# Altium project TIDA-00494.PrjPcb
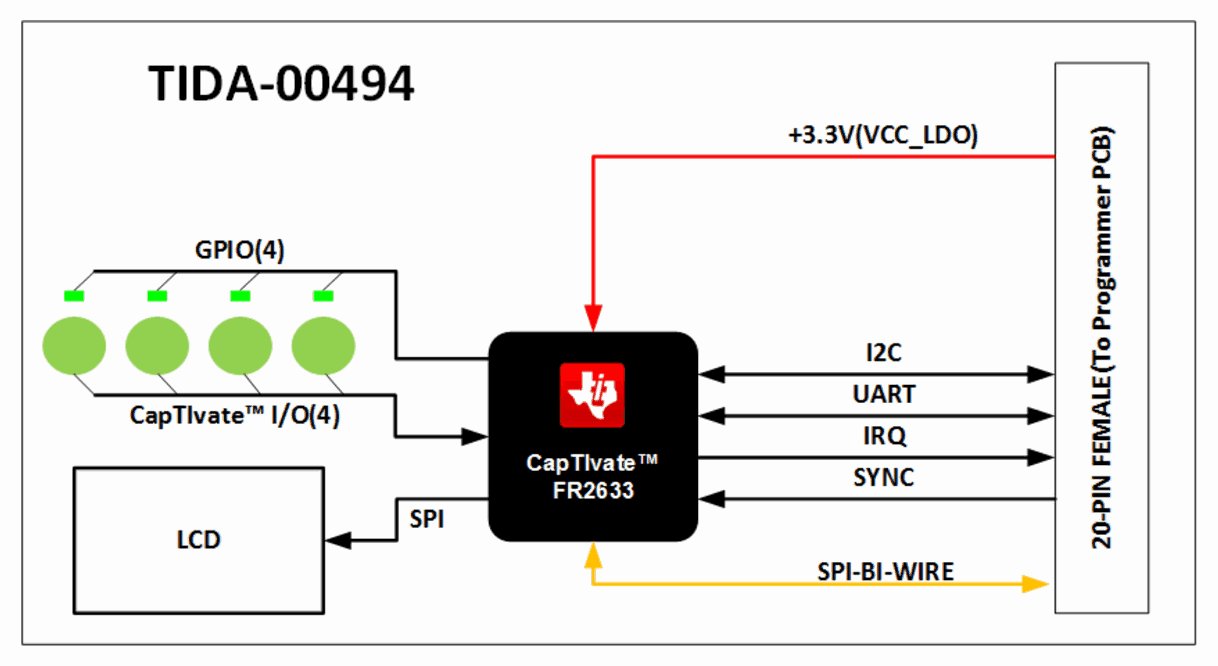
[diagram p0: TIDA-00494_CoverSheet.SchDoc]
CopyrightYear: 2016; PCB_Layout: Giovanni Campanella; PCB_Rev: E1; PRJ_Customer: Public Release; PRJ_Engineer: Giovanni Campanella; PRJ_Number: TIDA-00494; PRJ_Title: Touch through Glass with Display; SCH_Rev: E1; TechSupport: http://www.ti.com/support; TID: TIDA-00494
3 sheets, 49 parts. Net scope: global (net labels, ports and power ports of the same name join across sheets).
Board file: TIDA-00494.PcbDoc
Sheets:
  TIDA-00494_CoverSheet.SchDoc
  TIDA-00494_Schematic.SchDoc
  TIDA-00494_Hardware.SchDoc

## Sheet TIDA-00494_CoverSheet.SchDoc: Block Diagram TIDA-00494
size 431 x 279 mm; Date: Not shown in title block; ApprovedBy: Not shown in title block; CheckedBy: Not shown in title block; Author: Not shown in title block; CompanyName: Not shown in title block; DrawnBy: Giovanni Campanella; Engineer: Not shown in title block; Organization: Not shown in title block; Address1: Not shown in title block; Address2: Not shown in title block; Address3: Not shown in title block; Address4: Not shown in title block; DocumentNumber: 1; Revision: Use project parameter SCH_Rev; SheetNumber: 1; SheetTotal: 3; PageSetup: Record=PageOptions¦CenterHorizontal=True¦CenterVertical=True¦PrintScale=1.00¦XCorrection=1.00¦YCorrection=1.00¦PrintKind=0¦BorderSize=5000000¦LeftOffset=0¦BottomOffset=0¦Orientation=2¦PaperLength=1000¦PaperWidth=1000¦Scale=100¦PaperSource=15¦PrintQuality=600¦MediaType=1¦DitherType=10¦PaperKind=Letter¦PrintScaleMode=1

## Sheet TIDA-00494_Schematic.SchDoc: Schematic TIDA-00494
size 431 x 279 mm; Date: Not shown in title block; ApprovedBy: Not shown in title block; CheckedBy: Not shown in title block; Author: Not shown in title block; CompanyName: Not shown in title block; DrawnBy: Giovanni Campanella; Engineer: Not shown in title block; Organization: Not shown in title block; Address1: Not shown in title block; Address2: Not shown in title block; Address3: Not shown in title block; Address4: Not shown in title block; DocumentNumber: 2; Revision: Use project parameter SCH_Rev; SheetNumber: 2; SheetTotal: 3; PageSetup: Record=PageOptions¦CenterHorizontal=True¦CenterVertical=True¦PrintScale=1.00¦XCorrection=1.00¦YCorrection=1.00¦PrintKind=0¦BorderSize=5000000¦LeftOffset=0¦BottomOffset=0¦Orientation=2¦PaperLength=1000¦PaperWidth=1000¦Scale=100¦PaperSource=15¦PrintQuality=600¦MediaType=1¦DitherType=10¦PaperKind=Letter¦PrintScaleMode=1
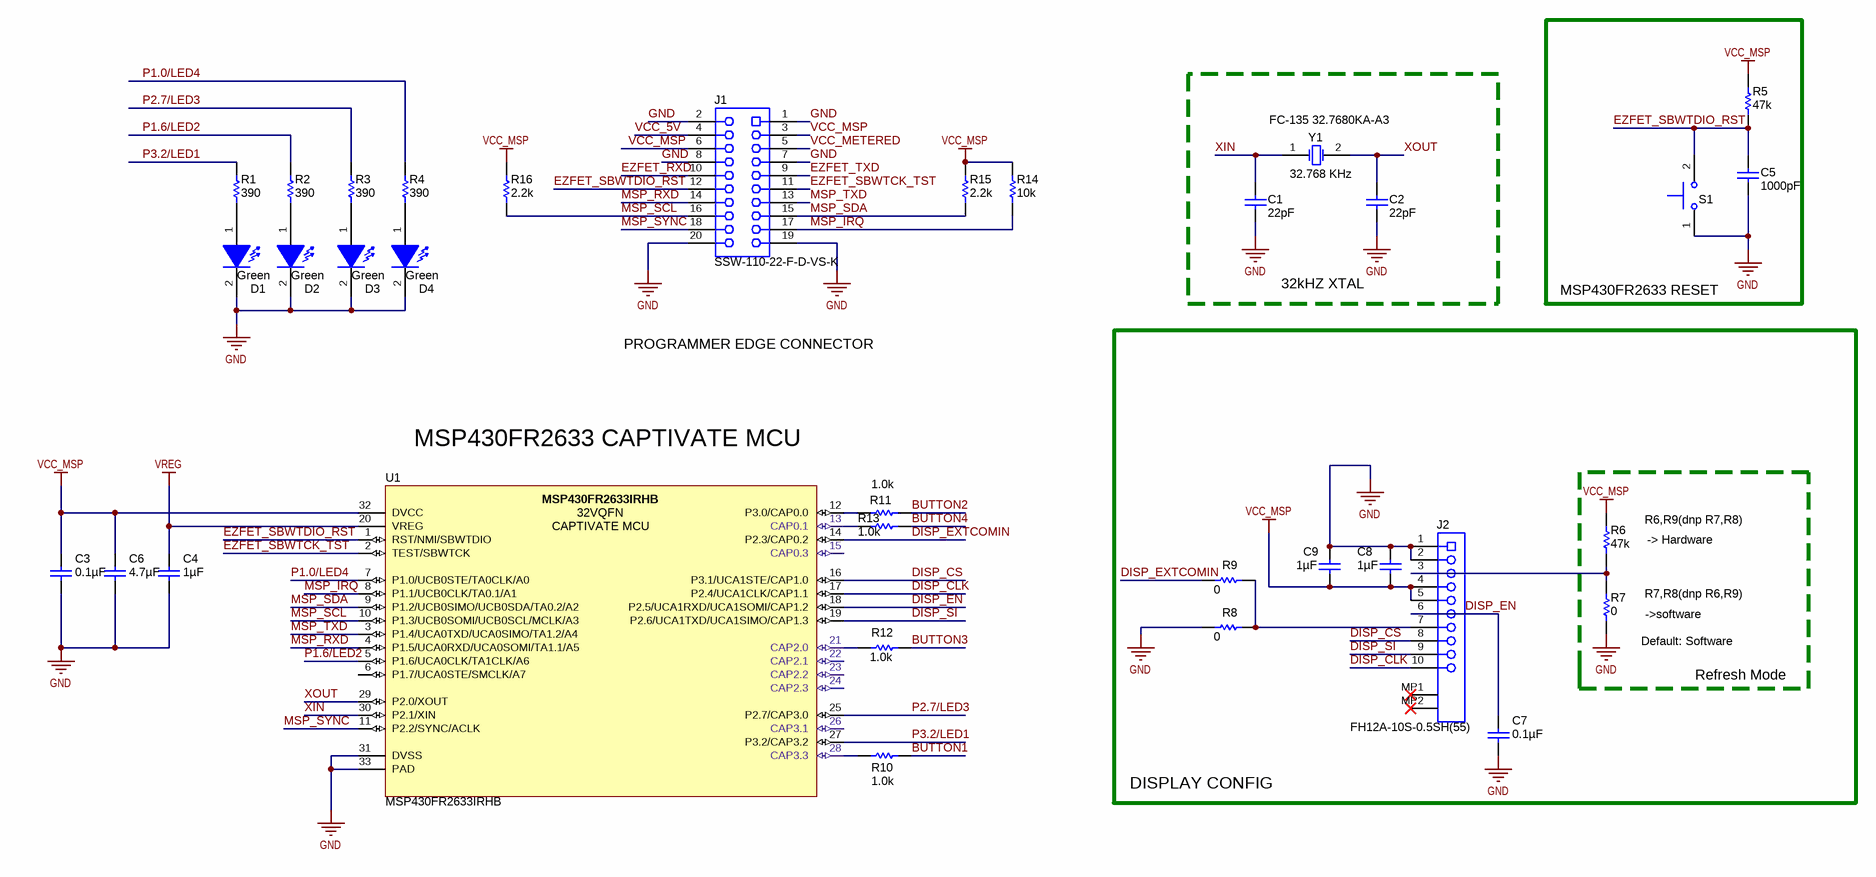
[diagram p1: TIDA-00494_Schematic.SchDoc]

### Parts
C1  ValueDisplayed: 22pF  [0402]  (hidden comment: GRM1555C1H220JA01D)
C2  ValueDisplayed: 22pF  [0402]  (hidden comment: GRM1555C1H220JA01D)
C3  ValueDisplayed: 0.1µF  [0402]  (hidden comment: C1005X5R1A104K)
C4  ValueDisplayed: 1µF  [0603]  (hidden comment: C1608X5R1A105K)
C5  ValueDisplayed: 1000pF  [0402]  (hidden comment: C1005X7R1H102K)
C6  ValueDisplayed: 4.7µF  [0603]  (hidden comment: C0603C475K8PACTU)
C7  ValueDisplayed: 0.1µF  [0402]  (hidden comment: C1005X5R1A104K)
C8  ValueDisplayed: 1µF  [0603]  (hidden comment: C1608X5R1A105K)
C9  ValueDisplayed: 1µF  [0603]  (hidden comment: C1608X5R1A105K)
D1  value Green  [LED_LTST-C190]  (hidden comment: LTST-C190GKT)
D2  value Green  [LED_LTST-C190]  (hidden comment: LTST-C190GKT)
D3  value Green  [LED_LTST-C190]  (hidden comment: LTST-C190GKT)
D4  value Green  [LED_LTST-C190]  (hidden comment: LTST-C190GKT)
J1  SSW-110-22-F-D-VS-K  [CONN_SSW-110-22-F-D-VS-K]
J2  FH12A-10S-0.5SH(55)  [Hirose_FH12A-10S-0_5SH[55]]
R1  value 390  [0402]  (hidden comment: CRCW0402390RJNED)
R2  value 390  [0402]  (hidden comment: CRCW0402390RJNED)
R3  value 390  [0402]  (hidden comment: CRCW0402390RJNED)
R4  value 390  [0402]  (hidden comment: CRCW0402390RJNED)
R5  value 47k  [0402]  (hidden comment: CRCW040247K0JNED)
R6  ValueDisplayed: 47k  [0402]  (hidden comment: CRCW040247K0JNED)
R7  ValueDisplayed: 0  [0402]  (hidden comment: CRCW04020000Z0ED)
R8  ValueDisplayed: 0  [0402]  (hidden comment: CRCW04020000Z0ED)
R9  ValueDisplayed: 0  [0402]  (hidden comment: CRCW04020000Z0ED)
R10  ValueDisplayed: 1.0k  [0402]  (hidden comment: CRCW04021K00JNED)
R11  ValueDisplayed: 1.0k  [0402]  (hidden comment: CRCW04021K00JNED)
R12  ValueDisplayed: 1.0k  [0402]  (hidden comment: CRCW04021K00JNED)
R13  ValueDisplayed: 1.0k  [0402]  (hidden comment: CRCW04021K00JNED)
R14  ValueDisplayed: 10k  [0402]  (hidden comment: CRCW040210K0JNED)
R15  ValueDisplayed: 2.2k  [0402]  (hidden comment: CRCW04022K20JNED)
R16  ValueDisplayed: 2.2k  [0402]  (hidden comment: CRCW04022K20JNED)
S1  SKRKAEE010  [SW_SKRKAEE010]  (value not drawn)
U1  MSP430FR2633IRHB  [RHB0032E]
Y1  FC-135 32.7680KA-A3  Frequency: 32.768 KHz  [Epson_FC-135]

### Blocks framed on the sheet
MSP430FR2633 RESET: C5 R5 S1
32kHZ XTAL: C1 C2 Y1
DISPLAY CONFIG: C7-C9 J2 R6-R9

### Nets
GND: C1.2 C2.2 C3.2 C4.2 C5.2 C6.2 C7.2 C8.1 C9.1 D1.2(K) D2.2(K) D3.2(K) D4.2(K) J1.1 J1.2 J1.7 J1.8 J1.19 J1.20 J2.1 J2.2 R7.1 R8.1 S1.1 U1.31(DVSS) U1.33(PAD)
VCC_MSP: C3.1 C6.1 C8.2 C9.2 J1.3 J1.6 J2.4 J2.5 R5.2 R6.2 R14.2 R15.2 R16.2 U1.32(DVCC)
VREG: C4.1 U1.20(VREG)
BUTTON1: R10.2
BUTTON2: R11.2
BUTTON3: R12.2
BUTTON4: R13.2
DISP_CLK: J2.10 U1.17(P2.4/UCA1CLK/CAP1.1)
DISP_CS: J2.8 U1.16(P3.1/UCA1STE/CAP1.0)
DISP_EN: C7.1 J2.6 U1.18(P2.5/UCA1RXD/UCA1SOMI/CAP1.2)
DISP_EXTCOMIN: R9.1 U1.14(P2.3/CAP0.2)
DISP_SI: J2.9 U1.19(P2.6/UCA1TXD/UCA1SIMO/CAP1.3)
EZFET_RXD: J1.10
EZFET_SBWTCK_TST: J1.11 U1.2(TEST/SBWTCK)
EZFET_SBWTDIO_RST: C5.1 J1.12 R5.1 S1.2 U1.1(RST/NMI/SBWTDIO)
EZFET_TXD: J1.9
MSP_IRQ: J1.17 R14.1 U1.8(P1.1/UCB0CLK/TA0.1/A1)
MSP_RXD: J1.14 U1.4(P1.5/UCA0RXD/UCA0SOMI/TA1.1/A5)
MSP_SCL: J1.16 R16.1 U1.10(P1.3/UCB0SOMI/UCB0SCL/MCLK/A3)
MSP_SDA: J1.15 R15.1 U1.9(P1.2/UCB0SIMO/UCB0SDA/TA0.2/A2)
MSP_SYNC: J1.18 U1.11(P2.2/SYNC/ACLK)
MSP_TXD: J1.13 U1.3(P1.4/UCA0TXD/UCA0SIMO/TA1.2/A4)
P1.0/LED4: R4.2 U1.7(P1.0/UCB0STE/TA0CLK/A0)
P1.6/LED2: R2.2 U1.5(P1.6/UCA0CLK/TA1CLK/A6)
P2.7/LED3: R3.2 U1.25(P2.7/CAP3.0)
P3.2/LED1: R1.2 U1.27(P3.2/CAP3.2)
VCC_5V: J1.4
VCC_METERED: J1.5
XIN: C1.1 U1.30(P2.1/XIN) Y1.1(OSC1)
XOUT: C2.1 U1.29(P2.0/XOUT) Y1.2(OSC2)
NetD1_1: D1.1(A) R1.1
NetD2_1: D2.1(A) R2.1
NetD3_1: D3.1(A) R3.1
NetD4_1: D4.1(A) R4.1
NetJ2_3: J2.3 R6.1 R7.2
NetJ2_7: J2.7 R8.2 R9.2
NetR10_1: R10.1 U1.28(CAP3.3)
NetR11_1: R11.1 U1.12(P3.0/CAP0.0)
NetR12_1: R12.1 U1.21(CAP2.0)
NetR13_1: R13.1 U1.13(CAP0.1)

Not connected (* = marked no-connect by the designer): J2 MP1* MP2*; U1 6(P1.7/UCA0STE/SMCLK/A7) 15(CAP0.3) 22(CAP2.1) 23(CAP2.2) 24(CAP2.3) 26(CAP3.1)

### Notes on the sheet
- PROGRAMMER EDGE CONNECTOR
- MSP430FR2633 CAPTIVATE MCU
- -> Hardware
- (near R6) R6,R9(dnp R7,R8)
- (near R7) ->software
- (near R7) Default: Software
- R7,R8(dnp R6,R9)
- Refresh Mode

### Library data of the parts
C1 C2 = GRM1555C1H220JA01D: CAP, CERM, 22 pF, 50 V, +/- 5%, C0G/NP0, 0402; Manufacturer: MuRata; Polarized: N; CompType: Capacitor; Value: 22pF; U/M: EA; Cap_F: 0.000000000022; Tolerance_%: 5; Value1: Unknown; VDC_V: 50; Value2: 50V; TaMin_C: -55; TaMax_C: 125
C3 C7 = C1005X5R1A104K: CAP, CERM, 0.1uF, 10V, +/-10%, X5R, 0402; Manufacturer: TDK; Polarized: N; CompType: Capacitor; U/M: EA; Cap_F: 0.0000001; Tolerance_%: 10; ESR_Ohm: 0.0186; Value1: 0.0186 ohm; TaMin_C: -55; TaMax_C: 85
C4 C8 C9 = C1608X5R1A105K: CAP, CERM, 1 µF, 10 V, +/- 10%, X5R, 0603; Manufacturer: TDK; Polarized: N; CompType: Capacitor; Value: 1uF; U/M: EA; Cap_F: 0.000001; Tolerance_%: 10; ESR_ohm: 0.0057; Value1: 0.0057 ohm; Value2: 10V; TaMin_C: -55; TaMax_C: 85
C5 = C1005X7R1H102K: CAP, CERM, 1000pF, 50V, +/-10%, X7R, 0402; Manufacturer: TDK; Polarized: N; CompType: Capacitor; U/M: EA; Cap_F: 0.000000001; Tolerance_%: 10; ESR_Ohm: 0.2381; Value1: 0.2381 ohm; VDC_V: 50; TaMin_C: -55; TaMax_C: 125
C6 = C0603C475K8PACTU: CAP, CERM, 4.7 µF, 10 V, +/- 10%, X5R, 0603; Manufacturer: Kemet; Polarized: N; CompType: Capacitor; Value: 4.7uF; U/M: EA; Cap_F: 0.0000047; Tolerance_%: 10; ESR_ohm: 0.006; Value1: 0.006 ohm; Value2: 10V; IRMS_A: 7.24; TaMin_C: -55; TaMax_C: 85; AEC Category: Q200
D1-D4 = LTST-C190GKT: LED, Green, SMD; Manufacturer: Lite-On; Vf_V: 2.1; Value2: 2.1V; Io_A: 0.02; Power_TotalModule: 0.1; Value1: 0.1W; U/M: EA
J1 = SSW-110-22-F-D-VS-K: Connector, Receptacle, 100mil, 10x2, Gold plated, SMD; Manufacturer: Samtec; SymbolCreator: a0412235
J2 = FH12A-10S-0.5SH(55): FFC Connector , Top, 0.5mm, 10x1, R/A, SMT; Manufacturer: Hirose Electric Co. Ltd.; SymbolCreator: Altium; Pitch_mm: 0.5; Gender: Female; Row_Count: 1; ContactFinish: Gold; Voltage_V: 50
R1-R4 = CRCW0402390RJNED: RES, 390 ohm, 5%, 0.063W, 0402; Manufacturer: Vishay-Dale; CompType: Resistor; Value_Code: 390R; Tolerance_%: 5; Power_W: 0.063; VDC_V: 50; TempCo: 200 ppm/C; EIA_Code: E24; U/M: EA
R5 = CRCW040247K0JNED: RES, 47k ohm, 5%, 0.063W, 0402; Manufacturer: Vishay-Dale; CompType: Resistor; Res_ohm: 47000; Value_Code: 47k0; Tolerance_%: 5; Power_W: 0.063; VDC_V: 50; TempCo: 200 ppm/C; EIA_Code: E24; U/M: EA
R6 = CRCW040247K0JNED: RES, 47 k, 5%, 0.063 W, 0402; Manufacturer: Vishay-Dale; CompType: Resistor; Value: 47k; Res_ohm: 47000; Value_Code: 47k0; Tolerance_%: 5; Power_W: 0.063; Value2: 0.063W; VDC_V: 50; TempCo: 200 ppm/C; EIA_Code: E24; U/M: EA; AEC Category: Q200
R7-R9 = CRCW04020000Z0ED: RES, 0, 5%, 0.063 W, 0402; Manufacturer: Vishay-Dale; CompType: Resistor; Value: 0; Value_Code: 0000; Tolerance_%: 5; Power_W: 0.063; Value2: 0.063W; VDC_V: 50; TempCo: 200 ppm/C; EIA_Code: E24; U/M: EA; AEC Category: Q200
R10-R13 = CRCW04021K00JNED: RES, 1.0 k, 5%, 0.063 W, 0402; Manufacturer: Vishay-Dale; CompType: Resistor; Value: 1.0k; Res_ohm: 1000; Value_Code: 1k00; Tolerance_%: 5; Power_W: 0.063; Value2: 0.063W; VDC_V: 50; TempCo: 200 ppm/C; EIA_Code: E24; U/M: EA; AEC Category: Q200
R14 = CRCW040210K0JNED: RES, 10 k, 5%, 0.063 W, 0402; Manufacturer: Vishay-Dale; CompType: Resistor; Value: 10k; Res_ohm: 10000; Value_Code: 10k0; Tolerance_%: 5; Power_W: 0.063; Value2: 0.063W; VDC_V: 50; TempCo: 200 ppm/C; EIA_Code: E24; U/M: EA
R15 R16 = CRCW04022K20JNED: RES, 2.2 k, 5%, 0.063 W, 0402; Manufacturer: Vishay-Dale; CompType: Resistor; Value: 2.2k; Res_ohm: 2200; Value_Code: 2k20; Tolerance_%: 5; Power_W: 0.063; Value2: 0.063W; VDC_V: 50; TempCo: 200 ppm/C; EIA_Code: E24; U/M: EA
S1 = SKRKAEE010: Switch, Push Button, SMD; Manufacturer: Alps; SymbolCreator: a0412235; Circuit: SPST-NO; VDC_V: 12; SwitchFunction: Off-Mom; PositionCount: 1; CurrentRating_mA: 50
U1 = MSP430FR2633IRHB: MSP430 Captivate Microcontroller; Manufacturer: Texas Instruments; SymbolCreator: W. Schnoor; CompType: IC; U/M: EA, IN, or GM
Y1 = FC-135 32.7680KA-A3: Crystal, 32.768 KHz, 12.5 pF, SMD; Manufacturer: Epson; SymbolCreator: a0412235; U/M: EA; TaMin_C: -40; TaMax_C: 85; Frequency Stability: ±20ppm

## Sheet TIDA-00494_Hardware.SchDoc: Hardware TIDA-00494
size 431 x 279 mm; Date: Not shown in title block; ApprovedBy: Not shown in title block; CheckedBy: Not shown in title block; Author: Not shown in title block; CompanyName: Not shown in title block; DrawnBy: Giovanni Campanella; Engineer: Not shown in title block; Organization: Not shown in title block; Address1: Not shown in title block; Address2: Not shown in title block; Address3: Not shown in title block; Address4: Not shown in title block; DocumentNumber: 3; Revision: Use project parameter SCH_Rev; SheetNumber: 3; SheetTotal: 3; PageSetup: Record=PageOptions¦CenterHorizontal=True¦CenterVertical=True¦PrintScale=1.00¦XCorrection=1.00¦YCorrection=1.00¦PrintKind=0¦BorderSize=5000000¦LeftOffset=0¦BottomOffset=0¦Orientation=2¦PaperLength=1000¦PaperWidth=1000¦Scale=100¦PaperSource=15¦PrintQuality=600¦MediaType=1¦DitherType=10¦PaperKind=Letter¦PrintScaleMode=1
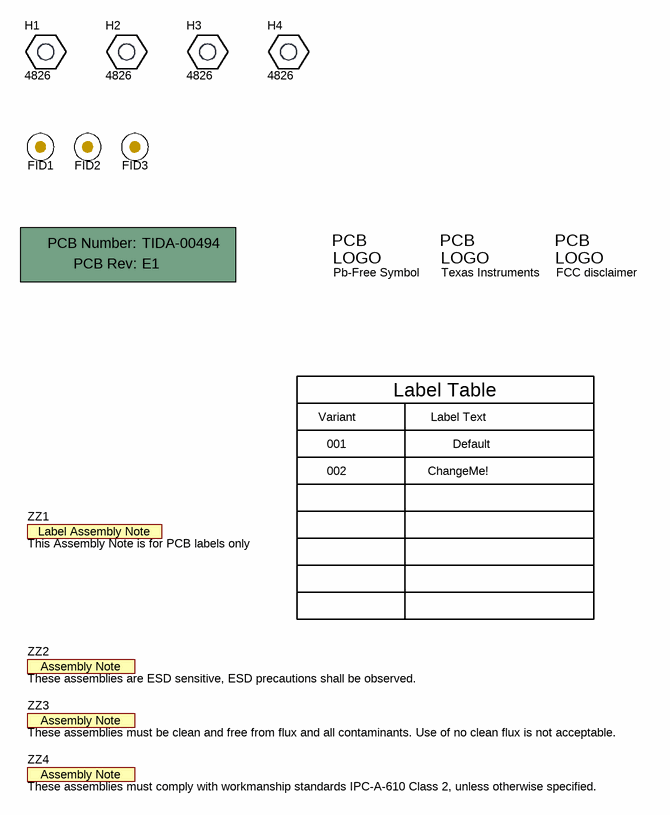
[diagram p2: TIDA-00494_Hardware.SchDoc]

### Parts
!PCB1  Printed Circuit Board  (value not drawn)  (mechanical)
FID1  Fiducial  [Fiducial10-20]  (value not drawn)
FID2  Fiducial  [Fiducial10-20]  (value not drawn)
FID3  Fiducial  [Fiducial10-20]  (value not drawn)
H1  4826  [KEYSTONE_4826]
H2  4826  [KEYSTONE_4826]
H3  4826  [KEYSTONE_4826]
H4  4826  [KEYSTONE_4826]
Logo1  Pb-Free Symbol  [Pb-Free_Overlay_Small]  (no BOM)
Logo2  Texas Instruments  [TI_Stacked_Overlay_Small]  (no BOM)
Logo3  FCC disclaimer  [FCC_disclaimer]  (no BOM)
ZZ1  This Assembly Note is for PCB labels only  [AssemblyNoteLabel]  (no BOM)
ZZ2  These assemblies are ESD sensitive, ESD precautions shall be observed.  [AssemblyNote]  (no BOM)
ZZ3  These assemblies must be clean and free from flux and all contaminants. Use of no clean flux is not acceptable.  [AssemblyNote]  (no BOM)
ZZ4  These assemblies must comply with workmanship standards IPC-A-610 Class 2, unless otherwise specified.  [AssemblyNote]  (no BOM)

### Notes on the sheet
- Label Table
- Variant
- 001
- 002
- Label Text
- ChangeMe!
- Default

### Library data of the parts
!PCB1 = PCB: Manufacturer: Any; PartNumber: TIDA-00494; SymbolCreator: a0412235
FID1-FID3 = Fiducial: Fiducial mark.  There is nothing to buy or mount.; SymbolCreator: codlsc
H1-H4 = 4826: HEX STANDOFF 6-32 NYLON 1-3/4"; Manufacturer: Keystone; SymbolCreator: a0412235
Logo1 = Pb-Free: SymbolCreator: a0412235
Logo2 = TI_Logo: Texas Instrument Corporate Signature; SymbolCreator: a0412235
Logo3 = FCC_disclaimer: SymbolCreator: codlsc
ZZ1 = AssemblyNoteLabel: SymbolCreator: a0412235
ZZ2-ZZ4 = AssemblyNote: SymbolCreator: codlsc

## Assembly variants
001: not fitted FID1 FID2 FID3 R6 R9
